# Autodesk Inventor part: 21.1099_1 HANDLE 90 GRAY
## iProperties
Created: 2007-02
Part Number: 21.1099_1 HANDLE 90 GRAY
Document SubType Name: Modeling
Designer: Andy Moles
Material: ABS Plastic
Mass: 24.3634 g
Surface Area: 104.492 cm^2
Volume: 22.9843 cm^3
Density: 1.06 g/cm^3
Author: Andy Moles
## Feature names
1. Fillet1
2. Fillet2
3. Fillet3
4. Fillet4
5. Fillet5
6. Fillet6
7. Base1
